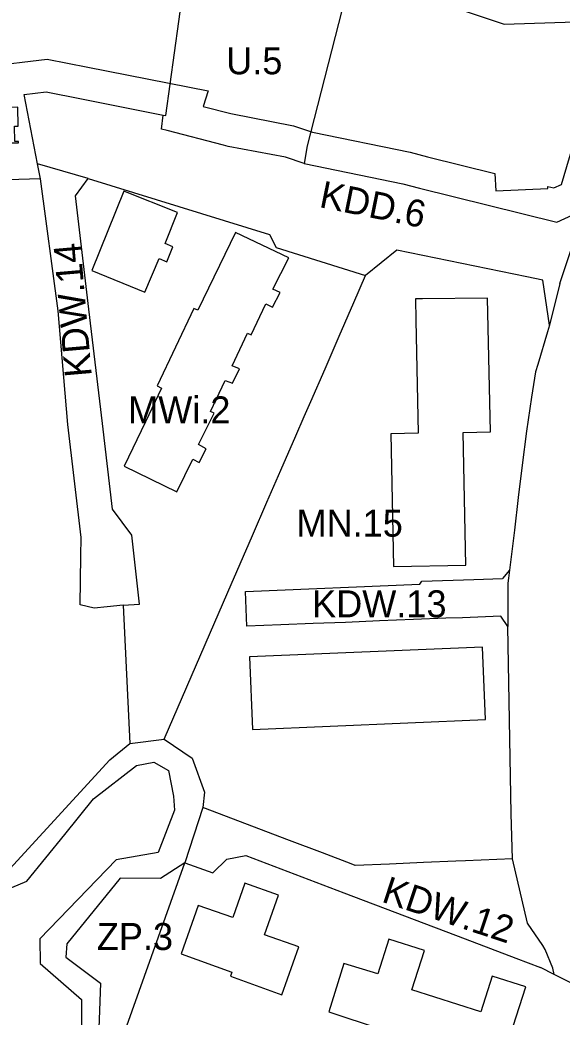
# Model space of a CAD drawing. Extents: x 7419601 to 7420547, y 5548907 to 5549873.
# Drawn here: x 7419779.2 to 7419879.6, y 5549211.8 to 5549396.6 of the extents above; entities that cross this region are included whole.
import ezdxf

# ---------------------------------------------------------------- set-up
doc = ezdxf.new("R2010")
doc.units = 0
for name, color, linetype in [('LIN_linie_rozgraniczajace', 7, 'Continuous'), ('LIN_nieprzekraczalna linia zabudowy', 7, 'Continuous'), ('LIN_obowiązująca linia zabudowy', 7, 'Continuous'), ('TXT_opisy_przeznaczen', 7, 'Continuous')]:
    doc.layers.add(name, color=color, linetype=linetype)

msp = doc.modelspace()

# ---------------------------------------------------------------- linework, layer by layer
at = {"layer": 'LIN_linie_rozgraniczajace'}
for p, q in [((7419791.85, 5549367.15), (7419782.48, 5549369.91)), ((7419879.24, 5549347.7), (7419883.76, 5549361.41)), ((7419798.35, 5549288.12), (7419799.55, 5549262.49)), ((7419799.55, 5549262.49), (7419805.9, 5549263.32))]:
    msp.add_line(p, q, dxfattribs=at)
for points in [[(7419866.43, 5549433.49), (7419858.54, 5549399.2), (7419868.91, 5549395.8), (7419893.34, 5549396.57), (7419894.15, 5549396.71)], [(7419806.26, 5549378.83), (7419810.27, 5549407.94), (7419825.48, 5549403.94), (7419839.54, 5549401.03), (7419832.39, 5549373.24), (7419831.86, 5549369.96)], [(7419798.35, 5549288.12), (7419795.36, 5549287.81), (7419792.97, 5549287.57), (7419790.35, 5549288.18), (7419790.49, 5549297.18), (7419790.55, 5549300.68), (7419788.06, 5549321.58), (7419786.31, 5549342.68), (7419783.04, 5549367.12), (7419782.48, 5549369.91), (7419780.01, 5549382.74), (7419784.06, 5549383.24), (7419790.63, 5549381.94), (7419805.73, 5549378.94), (7419806.26, 5549378.83)], [(7419806.5, 5549376.06), (7419805.43, 5549376.34), (7419805.73, 5549378.94)], [(7419831.86, 5549369.96), (7419828.38, 5549371.1), (7419817.8, 5549373.12), (7419816.92, 5549373.34), (7419806.5, 5549376.06)], [(7419831.86, 5549369.96), (7419850.13, 5549366.21), (7419853.2, 5549365.39), (7419878.68, 5549359.09), (7419883.76, 5549361.41)], [(7419798.35, 5549288.12), (7419801.37, 5549288.32), (7419799.91, 5549301.12), (7419796.38, 5549305.92), (7419794.49, 5549321.76), (7419791.99, 5549342.94), (7419789.53, 5549363.94), (7419791.85, 5549367.15), (7419825.44, 5549356.79)], [(7419825.44, 5549356.79), (7419826.68, 5549354.39), (7419843.23, 5549349.18)], [(7419877.3, 5549340), (7419876.06, 5549348.35), (7419873.1, 5549348.96), (7419849.05, 5549353.92), (7419843.23, 5549349.18)], [(7419805.9, 5549263.32), (7419817.74, 5549290.55), (7419822.3, 5549301.03), (7419824.97, 5549307.18), (7419827.56, 5549313.14), (7419830.32, 5549319.5), (7419831.87, 5549323.05), (7419833.1, 5549325.86), (7419835.72, 5549331.91), (7419838.36, 5549337.98), (7419841.08, 5549344.23), (7419843.23, 5549349.18)], [(7419879.24, 5549347.7), (7419877.3, 5549340), (7419876.93, 5549338.76), (7419875.14, 5549332.72), (7419874.73, 5549331.34), (7419873.98, 5549326.69), (7419873.01, 5549320.37), (7419872.25, 5549314.05), (7419871.52, 5549308.04), (7419870.79, 5549302.02), (7419869.89, 5549294.59), (7419868.57, 5549293.06)], [(7419869.89, 5549294.59), (7419869.71, 5549293.1), (7419869.61, 5549292.2), (7419869.57, 5549284.15)], [(7419869.57, 5549284.15), (7419868.29, 5549286.09), (7419861.18, 5549285.8), (7419858.11, 5549285.69), (7419852.11, 5549285.44), (7419845.82, 5549285.19), (7419839.52, 5549284.94), (7419833.53, 5549284.7), (7419827.53, 5549284.47), (7419821.24, 5549284.21), (7419820.97, 5549290.68), (7419853.29, 5549292.03), (7419853.67, 5549292.59), (7419863.29, 5549292.89), (7419868.57, 5549293.06)], [(7419870.44, 5549241.11), (7419870.22, 5549249.45), (7419869.57, 5549284.15)], [(7419764.51, 5549246.94), (7419767.98, 5549242.63), (7419769.9, 5549238.6), (7419772.6, 5549237.98), (7419777.35, 5549239.25), (7419795.85, 5549259.49), (7419799.55, 5549262.49)], [(7419805.9, 5549263.32), (7419811.1, 5549259.8), (7419813.41, 5549253.45), (7419813.11, 5549250.63)], [(7419773.26, 5549233.97), (7419780.51, 5549236.96), (7419787.54, 5549245.66), (7419792.81, 5549252.26), (7419800.81, 5549258.43), (7419804.03, 5549259.01), (7419806.71, 5549257.51), (7419807.68, 5549252.71), (7419807.84, 5549250.16), (7419804.83, 5549242.31), (7419797.03, 5549240.95), (7419782.91, 5549226.32), (7419782.94, 5549221.71), (7419790.59, 5549215.03), (7419790.54, 5549202.77)], [(7419813.11, 5549250.63), (7419809.73, 5549240.39)], [(7419870.44, 5549241.11), (7419861.75, 5549240.72), (7419859.93, 5549240.68), (7419853.94, 5549240.42), (7419847.64, 5549240.16), (7419841.33, 5549239.89), (7419840.54, 5549240.2), (7419835.25, 5549242.21), (7419829.15, 5549244.53), (7419813.11, 5549250.63)], [(7419809.73, 5549240.39), (7419805.23, 5549237.47), (7419797.75, 5549237.54), (7419787.92, 5549225.4), (7419787.71, 5549222.91), (7419794.15, 5549218.11), (7419793.89, 5549211.36), (7419793.48, 5549200.93)], [(7419923.28, 5549166.59), (7419908.23, 5549171.95), (7419898.64, 5549174.86), (7419889.05, 5549177.79), (7419881.72, 5549180.02), (7419873.89, 5549182.79), (7419859.94, 5549187.69), (7419850.51, 5549191.02), (7419841.07, 5549194.35), (7419826.44, 5549199.51), (7419812.76, 5549204.33), (7419798.71, 5549209.29), (7419809.73, 5549240.39)], [(7419809.73, 5549240.39), (7419814.92, 5549238.55), (7419817.52, 5549241.03), (7419821.06, 5549241.72), (7419839.19, 5549234.83), (7419861.68, 5549226.27), (7419871.04, 5549222.7), (7419875.61, 5549220.97)], [(7419878.14, 5549219.72), (7419877.92, 5549220.86), (7419876.47, 5549224.32), (7419876.06, 5549225.09), (7419873.24, 5549229.19), (7419870.44, 5549241.11)], [(7419932.6, 5549204.46), (7419924.26, 5549206.56), (7419908.56, 5549210.52), (7419884.53, 5549216.57), (7419878.14, 5549219.72), (7419875.61, 5549220.97)]]:
    msp.add_lwpolyline(points, dxfattribs=at)
at = {"layer": 'LIN_nieprzekraczalna linia zabudowy'}
for points in [[(7419879.51, 5549366.06), (7419885.32, 5549385.64), (7419887.98, 5549396.4)], [(7419783.04, 5549367.12), (7419776.97, 5549366.9), (7419775.64, 5549373.76), (7419778.92, 5549373.8), (7419778.92, 5549374.02), (7419778.26, 5549374.01), (7419778.22, 5549376.85), (7419778.88, 5549376.86), (7419778.83, 5549380.38), (7419774.93, 5549380.33), (7419774.92, 5549381.4), (7419775.73, 5549381.41), (7419777.07, 5549385.31), (7419776.64, 5549385.45), (7419776.18, 5549384.12), (7419773.64, 5549384.09), (7419772.9, 5549387.91), (7419784.28, 5549389.31), (7419791.8, 5549387.83), (7419814.1, 5549383.39)], [(7419814.1, 5549383.39), (7419813.15, 5549380.53)], [(7419813.15, 5549380.53), (7419818.25, 5549379.19), (7419829.9, 5549376.92), (7419833.4, 5549375.77)], [(7419833.4, 5549375.77), (7419851.51, 5549372.05), (7419854.69, 5549371.2), (7419867.19, 5549368.11), (7419867.34, 5549364.92), (7419877.01, 5549365.3), (7419877, 5549365.69), (7419878.09, 5549365.42), (7419879.51, 5549366.06)]]:
    msp.add_lwpolyline(points, dxfattribs=at)
at = {"layer": 'LIN_obowiązująca linia zabudowy'}
for p, q in [((7419853.75, 5549344.87), (7419852.46, 5549344.85)), ((7419852.46, 5549344.85), (7419852.53, 5549340.95)), ((7419865.81, 5549345.03), (7419853.75, 5549344.87)), ((7419866.35, 5549320.24), (7419865.81, 5549345.03)), ((7419852.53, 5549340.95), (7419852.97, 5549319.96)), ((7419852.97, 5549319.96), (7419847.91, 5549319.86)), ((7419847.91, 5549319.86), (7419848.42, 5549295.26)), ((7419861.29, 5549320.13), (7419866.35, 5549320.24)), ((7419861.8, 5549295.53), (7419861.29, 5549320.13)), ((7419848.42, 5549295.26), (7419861.8, 5549295.53)), ((7419864.88, 5549280.32), (7419821.75, 5549278.55)), ((7419865.43, 5549266.94), (7419864.88, 5549280.32)), ((7419821.75, 5549278.55), (7419822.3, 5549265.11)), ((7419822.3, 5549265.11), (7419865.43, 5549266.94)), ((7419820.85, 5549236.64), (7419818.64, 5549230.24)), ((7419827.08, 5549234.41), (7419820.85, 5549236.64)), ((7419824.51, 5549227.03), (7419827.08, 5549234.41)), ((7419812.22, 5549232.49), (7419809.08, 5549223.49)), ((7419818.64, 5549230.24), (7419812.22, 5549232.49)), ((7419830.86, 5549224.83), (7419824.51, 5549227.03)), ((7419847.51, 5549226.22), (7419845.49, 5549219.83)), ((7419854.13, 5549224.12), (7419847.51, 5549226.22)), ((7419827.71, 5549215.94), (7419830.86, 5549224.83)), ((7419851.83, 5549216.84), (7419854.13, 5549224.12)), ((7419809.08, 5549223.49), (7419818.46, 5549220.11)), ((7419839.22, 5549221.73), (7419836.45, 5549212.76)), ((7419845.49, 5549219.83), (7419839.22, 5549221.73)), ((7419818.46, 5549220.11), (7419818.2, 5549219.41)), ((7419818.2, 5549219.41), (7419827.71, 5549215.94)), ((7419866.65, 5549219.38), (7419864.56, 5549212.8)), ((7419872.91, 5549217.4), (7419866.65, 5549219.38)), ((7419864.56, 5549212.8), (7419851.83, 5549216.84)), ((7419870.59, 5549210.09), (7419872.91, 5549217.4)), ((7419836.45, 5549212.76), (7419845.92, 5549209.65))]:
    msp.add_line(p, q, dxfattribs=at)
for points in [[(7419792.54, 5549350.16), (7419802.37, 5549346.11), (7419805, 5549352.36), (7419806.41, 5549351.74), (7419807.53, 5549354.49), (7419806.12, 5549355.12), (7419808.42, 5549360.9), (7419798.44, 5549364.82)], [(7419812.17, 5549342.76), (7419811.44, 5549343.1), (7419804.61, 5549328.74), (7419805.43, 5549328.31), (7419802.45, 5549322.06), (7419798.54, 5549313.86), (7419808.3, 5549309.15), (7419811.23, 5549315.16), (7419812.44, 5549314.53), (7419813.68, 5549317.11), (7419812.31, 5549317.86), (7419815.19, 5549323.68), (7419814.51, 5549324), (7419817.23, 5549329.76), (7419818.59, 5549329.25), (7419819.88, 5549331.88), (7419818.53, 5549332.47), (7419821.36, 5549338.5), (7419822.05, 5549338.22), (7419824.73, 5549343.96), (7419826.01, 5549343.34), (7419827.4, 5549346.03), (7419826.06, 5549346.65), (7419828.99, 5549352.5), (7419819.13, 5549357.18)]]:
    msp.add_lwpolyline(points, close=True, dxfattribs=at)

# ---------------------------------------------------------------- texts
at = {"layer": 'TXT_opisy_przeznaczen'}
for s, p in [('U.5', (7419817.42, 5549386.48)), ('MWi.2', (7419799.26, 5549321.8)), ('MN.15', (7419830.44, 5549300.81)), ('KDW.13', (7419833.33, 5549285.87)), ('ZP.3', (7419793.45, 5549224.23))]:
    msp.add_text(s, height=5, dxfattribs=at).set_placement(p)
for s, rotation, p in [('KDD.6', 348.5334, (7419834.47, 5549361.9)), ('KDW.14', 94.9513, (7419792.54, 5549330.59)), ('KDW.12', 341.6605, (7419846, 5549233.22))]:
    msp.add_text(s, height=5, rotation=rotation, dxfattribs=at).set_placement(p)

doc.saveas('drawing.dxf')
